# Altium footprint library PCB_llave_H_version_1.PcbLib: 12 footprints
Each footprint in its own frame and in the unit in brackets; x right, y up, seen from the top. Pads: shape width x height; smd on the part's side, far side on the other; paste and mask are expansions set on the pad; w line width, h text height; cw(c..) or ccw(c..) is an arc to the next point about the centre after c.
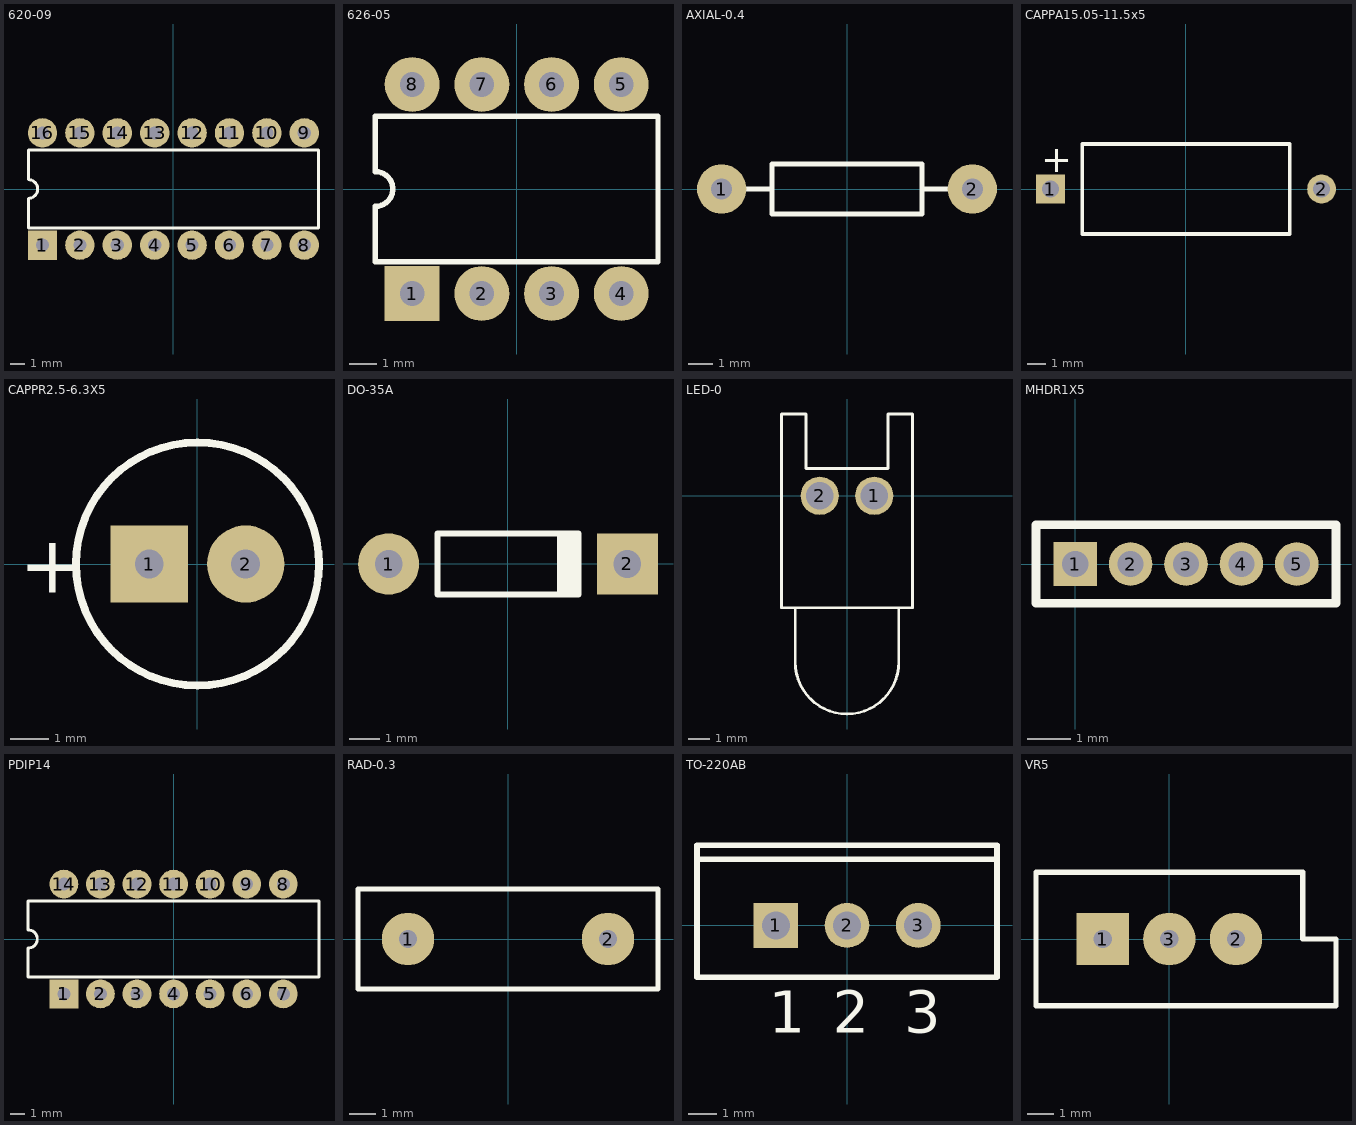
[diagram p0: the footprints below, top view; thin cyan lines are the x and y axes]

## 620-09 [mm] "DIP; 16 Leads; Row Spacing 7.62 mm; Pitch 2.54 mm"
height 4.19
pads (16):
  rect 2x2 hole 0.9: 1(-8.89,-3.81)
  round 2 hole 0.9: 2(-6.35,-3.81) 3(-3.81,-3.81) 4(-1.27,-3.81) 5(1.27,-3.81) 6(3.81,-3.81) 7(6.35,-3.81) 8(8.89,-3.81) 9(8.89,3.81) 10(6.35,3.81) 11(3.81,3.81) 12(1.27,3.81) 13(-1.27,3.81) 14(-3.81,3.81) 15(-6.35,3.81) 16(-8.89,3.81)
Top Overlay:
  lines w0.2: -9.85,-2.65 9.85,-2.65 9.85,2.65 -9.85,2.65 -9.85,0.635 cw(c-9.85,0) -9.85,-0.635 -9.85,-2.65

## 626-05 [mm] "DIP; 8 Leads; Row Spacing 7.62 mm; Pitch 2.54 mm"
height 4.45
pads (8):
  rect 2x2 hole 0.9: 1(-3.81,-3.81)
  round 2 hole 0.9: 2(-1.27,-3.81) 3(1.27,-3.81) 4(3.81,-3.81) 5(3.81,3.81) 6(1.27,3.81) 7(-1.27,3.81) 8(-3.81,3.81)
Top Overlay:
  lines w0.2: -5.15,-2.65 -5.15,-0.635 ccw(c-5.15,0) -5.15,0.635 -5.15,2.65 5.15,2.65 5.15,-2.65 -5.15,-2.65

## AXIAL-0.4 [mm] "Resistor; 2 Leads"
height 2.032
pads (2):
  round 2 hole 0.85: 1(-5.08,0) 2(5.08,0)
Top Overlay:
  lines w0.2: -4.064,0 -3.048,0 ; 3.048,0 4.064,0 ; -3.048,-1.016 3.048,-1.016 3.048,1.016 -3.048,1.016 -3.048,-1.016

## CAPPA15.05-11.5x5 [mm] "Capacitor, Electrolytic, Axial; Body 11.5 x 5 mm (LxDia. max), Lead Dia. 0.6 mm (typ)"
height 5
pads (2):
  rect 1.6x1.6 hole 0.95: 1(-7.525,0)
  round 1.6 hole 0.95: 2(7.525,0)
Top Overlay:
  lines w0.2: -5.75,-2.5 -5.75,2.5 5.75,2.5 5.75,-2.5 -5.75,-2.5
  text "+" at -8.025,0.925 h1.5

## CAPPR2.5-6.3X5 [mm] "Capacitor, Electrolytic, Radial; Body 6.3 x 5 mm (Dia.xH typ); Pin Spacing 2.5 mm (typ)"
height 6
pads (2):
  rect 2x2 hole 0.75: 1(-1.25,0)
  round 2 hole 0.75: 2(1.25,0)
Top Overlay:
  circle w0.2: c0,0 r3.15
  text "+" at -4.625,-0.75 h1.5

## DO-35A [mm] "Diode, Axial; Body 4.6 x 1.9 mm (LxDia. max), Lead Dia. 0.53 mm (max)"
height 2
pads (2):
  round 2 hole 0.9: 1(-3.9,0)
  rect 2x2 hole 0.9: 2(3.9,0)
Top Overlay:
  rectangle: 1.6,-1 2.4,1
  lines w0.2: 2.3,-1 -2.3,-1 -2.3,1 2.3,1

## LED-0 [mil] "Typical INFRARED GaAs LED; 2 Leads"
pads (2):
  round 70 hole 50: 1(50,0) 2(-50,0)
Top Overlay:
  lines w5: -95,-205 -95,-305 ccw(c0,-305) 95,-305 95,-205 ; -120,-205 120,-205 120,150 75,150 75,50 -75,50 -75,150 -120,150 -120,-205

## MHDR1X5 [mm] "Connector; Header; 5 Position"
pads (5):
  rect 1x1 hole 0.6: 1(0,0)
  round 1 hole 0.6: 2(1.27,0) 3(2.54,0) 4(3.81,0) 5(5.08,0)
Top Overlay:
  lines w0.2: -0.9,-0.9 5.98,-0.9 5.98,0.9 -0.9,0.9 -0.9,-0.9

## PDIP14 [mm] "DIP; 14 Leads; Row Spacing 7.62 mm; Pitch 2.54 mm"
height 5.33
pads (14):
  rect 2x2 hole 0.9: 1(-7.62,-3.81)
  round 2 hole 0.9: 2(-5.08,-3.81) 3(-2.54,-3.81) 4(0,-3.81) 5(2.54,-3.81) 6(5.08,-3.81) 7(7.62,-3.81) 8(7.62,3.81) 9(5.08,3.81) 10(2.54,3.81) 11(0,3.81) 12(-2.54,3.81) 13(-5.08,3.81) 14(-7.62,3.81)
Top Overlay:
  lines w0.2: -10.1,-2.65 -10.1,-0.635 ccw(c-10.1,0) -10.1,0.635 -10.1,2.65 10.1,2.65 10.1,-2.65 -10.1,-2.65

## RAD-0.3 [mm] "Capacitor; 2 Leads"
height 6
pads (2):
  round 2 hole 0.7: 1(-3.81,0) 2(3.81,0)
Top Overlay:
  lines w0.2: -5.715,-1.905 -5.715,1.905 5.715,1.905 5.715,-1.905 -5.715,-1.905

## TO-220AB [mm] "TO, Thru-Hole, Vertical, Heatsink Mounted; 3 In-Line Leads; Pitch 2.54 mm"
height 19.3
pads (3):
  rect 1.6x1.6 hole 1: 1(-2.54,0)
  round 1.6 hole 1: 2(0,0) 3(2.54,0)
Top Overlay:
  lines w0.2: -5.35,2.35 5.35,2.35 ; -5.35,-1.85 -5.35,2.85 5.35,2.85 5.35,-1.85 -5.35,-1.85
  text "3" at 2.04,-3.825 h1.5
  text "1" at -2.79,-3.825 h1.5
  text "2" at -0.5,-3.825 h1.5

## VR5 [mm] "Potentiometer; 3 Leads"
pads (3):
  rect 2x2 hole 0.7: 1(-2.54,0)
  round 2 hole 0.7: 2(2.54,0) 3(0,0)
Top Overlay:
  lines w0.2: -5.08,-2.54 6.35,-2.54 6.35,0 5.08,0 5.08,2.54 -5.08,2.54 -5.08,-2.54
